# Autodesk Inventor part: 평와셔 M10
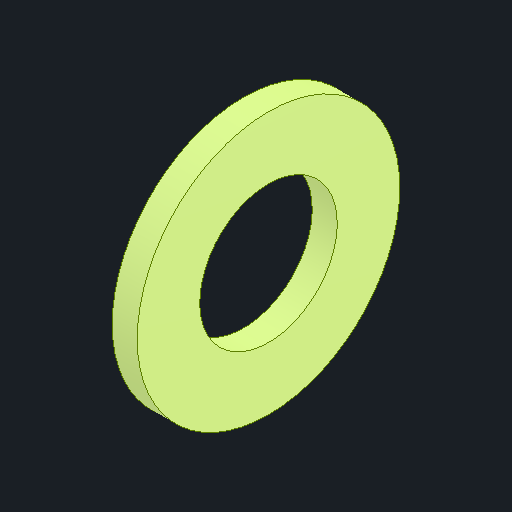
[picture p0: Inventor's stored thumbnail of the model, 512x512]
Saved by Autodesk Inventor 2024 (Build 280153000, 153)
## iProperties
Created: 2025-02
Part Number: 평와셔 M10
Material: 강철, 연강
Description: 평면 와셔
Document SubType Name: Modeling
Designer: kh_501
Density: 7.85 g/cm^3
Appearance: 기본값
Author: jhkim
Sending System: Autodesk Inventor 2025
Preprocessor: ST-DEVELOPER v20
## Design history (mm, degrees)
feature "Solid1"
node "솔리드1"
